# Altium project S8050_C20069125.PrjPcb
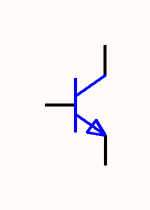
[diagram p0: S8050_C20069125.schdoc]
1 sheet, 1 parts. Net scope: global (net labels, ports and power ports of the same name join across sheets).

## Sheet S8050_C20069125.schdoc
size 127 x 101 mm

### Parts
Q?  s8050_c20069125  [SOT-23-3_L2.9-W1.3-P1.90-LS2.3-BR]  (value not drawn)

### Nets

Not connected (* = marked no-connect by the designer): Q? 1(B) 2(E) 3(C)

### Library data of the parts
Q? = s8050_c20069125: 晶体管类型:NPN;集电极电流(Ic):500mA;集射极击穿电压(Vceo):25V;耗散功率(Pd):300mW;直流电流增益(hFE):120;; Manufacturer: R+O(宏嘉诚); ManufacturerPart: S8050; AddInBom: yes; ModelId: 5504beb8757f4de79731898ec55d3e54; ModelTransform: 114.173,90.551,0,90,0,0,0,0,0; type: NPN; Current - Collector(Ic): 500mA; Collector - Emitter Voltage VCEO: 25V; Pd - Power Dissipation: 300mW; DC Current Gain: 120; Transition frequency(fT): 100MHz; Current - Collector Cutoff: 100nA; Vce Saturation(VCE(sat)): 600mV; Emitter-Base Voltage(Vebo): 5V; Number: 1个NPN; Configuration: 独立式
